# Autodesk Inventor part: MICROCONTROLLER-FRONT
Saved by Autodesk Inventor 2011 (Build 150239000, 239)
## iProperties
Created: 2007-09
Part Number: MICROCONTROLLER-FRONT
Document SubType Name: Modeling
Density: 1 g/cm^3
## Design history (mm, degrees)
feature "Base1"
body "Solid1"
